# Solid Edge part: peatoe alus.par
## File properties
Author: Georg
Template: Iso Part.par
Last saved by: Georg
Revision: 2
Application: Solid Edge
Accuracy: 0,990
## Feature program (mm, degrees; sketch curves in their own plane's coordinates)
sketch for "unnamed Protrusion 1" plane through (0, 0, 0) normal (0, 0, 1) x-axis (1, 0, 0)
  line (-15, -12.5) -> (15, -12.5)
  line (15, -12.5) -> (15, 12.5)
  line (15, 12.5) -> (-15, 12.5)
  line (-15, 12.5) -> (-15, -12.5)
  dimension (linear) = 15
  dimension (linear) = 15
extrude "unnamed Protrusion 1" add finite 16 along +normal
sketch for "ExtrudedCutout_1" plane through (15, 0, 8) normal (1, 0, 0) x-axis (0, 1, 0)
  line (6.5, 8) -> (12.5, -8)
  line (0, 8) -> (6.5, 8)
  line (0, 8) -> (-6.5, 8)
  line (-6.5, 8) -> (-12.5, -8)
extrude "ExtrudedCutout_1" cut finite 112.9998 along -normal
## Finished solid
Body 1: solid body, 6 faces, 12 edges, 8 vertices.
  Faces by surface: plane 6
  Edges by curve: line 12
Bounding box of the edges (mm): 30.000 x 25.000 x 16.000, from (-15, -12.5, 0) to (15, 12.5, 16).
Planar faces by outward normal: +x 1, +z 1, -x 1, -z 1, oblique 2
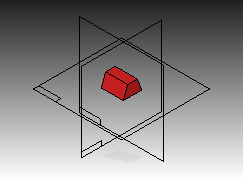
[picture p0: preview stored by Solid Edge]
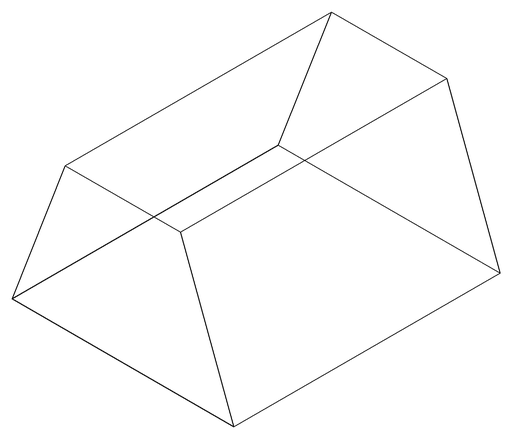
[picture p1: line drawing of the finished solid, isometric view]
